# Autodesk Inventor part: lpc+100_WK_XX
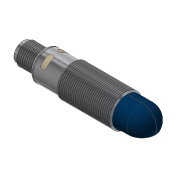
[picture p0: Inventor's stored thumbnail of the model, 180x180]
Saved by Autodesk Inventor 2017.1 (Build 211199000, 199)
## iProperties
Shininess: 20.0
Length Units: 11269
Angle Units: 11279
Time Units: 11290
Mass Units: 11283
Length Display Precision: 2
Angle Display Precision: 2
Part Number: lpc+100_WK_XX
Material: Nichtrostender Stahl - 440C
Document SubType Name: Modellieren
Description: Ipc-25 /CXX/M18
Checked By: Alves
Created: 2005-08
Designer: Ohle
Manufacturer: Standard
Standards Organization: Custom
Appearance: Aluminium - poliert
Density: 0.0
Volumn: 0.0
Area: 0.0
PropertySet Name: Model Information
Control State: 0
Master: False
Checked Out: False
BESTELLNUMMER: Ipc-25 /CXX/M18
ME: ST
Title: Ipc Sensoren
Author: Ohle
Comments: keine Bemerkung
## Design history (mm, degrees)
sketch "Skizze10"
  geometry: L1 (-43.018, 0)-(22.982, 0); L2 (-39.018, 6.5)-(-39.018, 7.25); L3 (-45.9, 8)-(-45.9, 8); L4 (-23.268, 9)-(5.732, 9); L5 (1.482, 0)-(-82.2, 0); L6 (-24.018, 8.25)-(-23.268, 9); L7 (6.482, 8.25)-(5.732, 9); L8 (-50.518, 6)-(-39.518, 6); L9 (-37.418, 8.25)-(-24.018, 8.25); L10 (-51.018, 4.5)-(-43.018, 4.5); L11 (-43.018, 0)-(-43.018, 4.5); L12 (-37.518, 8.25)-(-38.018, 8.25); L13 (-39.518, 6)-(-39.018, 6.5); L14 (-51.018, 5.5)-(-51.018, 4.5); L15 (-51.018, 5.5)-(-50.518, 6); L16 (-37.518, 8.25)-(-37.518, 8.15); L17 (-37.518, 8.15)-(-37.418, 8.15); L18 (-37.418, 8.15)-(-37.418, 8.25); L19 (6.482, 8.25)-(14.732, 8.25); L20 (22.982, 0)-(22.982, 0); A1 r 1 centre (-38.018, 7.25) between (-38.018, 8.25) and (-39.018, 7.25); A2 r 8.25 centre (14.732, 0) between (22.982, 0) and (14.732, 8.25); 4 further points
  constraints: 41 end point, 8 point on line, 5 parallel, 4 perpendicular, 4 point on circle, 4 tangent, 2 centre point, 2 horizontal, 1 collinear
  dimensions: "d171" = 4.5 distance between parallel lines of L10 L1; "d250" = 0.75 distance from line of L7.start L4; "d256" = 45 deg angle of L4 L6; "d257" = 8.25 distance between parallel lines of L5 L9; "d263" = 8.25 distance between parallel lines of L5 L12; "d266" = 12 distance from line of L2 L14.start; "d269" = 6 distance between parallel lines of L5 L8; "d289" = 135 deg angle of L7 L4; "d290" = 0.5 horizontal distance of L8.end L2.start; "d291" = 45 deg angle of L13 L8 (derived); "d293" = 0.5 horizontal distance of L14.start L8.start; "d294" = 45 deg angle of L15 L8 (derived); "d295" = 8 distance of L10.start L10.end; "d296" = 1.5 distance of L12.start point (-39.018, 8.25); "d297" = 0.1 distance of L16.end L17.end; "d298" = 8.15 distance between parallel lines of L17 L1; "d299" = 15 distance from line of L6.start L2; "d300" = 1 radius of A1; "d338" = 8.25 radius of A2; "d339" = 16.5 horizontal distance of L20.end L7.start; "d340" = 8.25 distance between parallel lines of L1 L19 (derived); "d365" = 30.5 distance of L7.start L6.start
revolve "Grundkörper pico+" sketch "Skizze10" stored, may be unused: angle "d168" = 90 deg
feature "Gewinde M12" dims "d174" = 10, "d175" = 0
feature "Gewinde M 18" dims "d179" = 10, "d180" = 0
workplane "Arbeitsebene1"
workplane "Arbeitsebene2"
sketch "Skizze13"
  geometry: L1 (-3.409, -3.409)-(3.61, 3.61); L2 (-3.439, 3.439)-(4.105, -4.105); L3 (-12.6, 0)-(12.6, 0) reference; C1 r 0.5 at (2.121, -2.121); C2 r 0.5 at (2.121, 2.121); C3 r 0.5 at (-2.121, 2.121); C4 r 0.5 at (-2.121, -2.121); C5 r 4.5 at (0, 0) reference; C6 r 0.5 at (0, 0); A1 r 3 centre (0, 0) between (-2.121, 2.121) and (2.121, 2.121); 2 further points
  constraints: 6 centre point, 6 point on line, 4 coincident, 4 end point, 4 equal radius, 4 point on circle, 1 horizontal alignment, 1 perpendicular
  dimensions: "d208" = 1 diameter of C3; "d209" = 6 diameter of A1
extrude "Pole" join sketch "Skizze13" distance "d212" = 7; taper "d213" = 0 deg
fillet "Rundung Pole" dims "d214" = 0.5
sketch "Skizze14"
  geometry: C1 r 0.5 at (0, -4.5); A1 r 4.5 centre (0, 0) between (4.435, -0.762) and (4.435, 0.762); A2 r 4.5 centre (0, 0) between (0, 4.5) and (0.499, 4.472) reference; A3 r 0.5 centre (0, 4.5) between (-0.499, 4.472) and (0.499, 4.472); 3 further points
  constraints: 9 point on circle, 3 centre point, 3 coincident, 1 horizontal alignment, 1 vertical alignment
  dimensions: "d215" = 9 diameter of A1; "d280" = 1 diameter of A3; "d330" = 1 diameter of C1
extrude "Verdrehsicherung" join sketch "Skizze14" distance "d217" = 7; taper "d218" = 0 deg
sketch "Skizze18"
  geometry: C1 r 7.25 at (0, 0) reference; C2 r 1 at (-8.15, 0)
  constraints: 1 centre point, 1 horizontal alignment
  dimensions: "d328" = 2 diameter of C2; "d329" = 8.15 distance of C1.centre C2.centre
extrude "Bohrung Ausrichtung" cut sketch "Skizze18" distance "d316" = 0.75; taper "d317" = 0 deg
workplane "Arbeitsebene4"
sketch "Skizze19"
  geometry: L1 (-39.018, 0)-(-30.18, 0); L2 (-34.718, -7.5)-(-34.718, -3); L3 (-31.718, -7.5)-(-31.718, -3); L4 (-31.718, 3)-(-31.718, 7.5); L5 (-34.718, 3)-(-34.718, 7.5); A1 r 1.5 centre (-33.218, 3) between (-31.718, 3) and (-34.718, 3); A2 r 1.5 centre (-33.218, -3) between (-34.718, -3) and (-31.718, -3); A3 r 1.5 centre (-33.218, 7.5) between (-31.718, 7.5) and (-34.718, 7.5); A4 r 1.5 centre (-33.218, -7.5) between (-34.718, -7.5) and (-31.718, -7.5); 4 further points; 1 other entity
  constraints: 10 end point, 8 point on circle, 8 tangent, 4 centre point, 3 equal radius, 2 vertical alignment, 1 horizontal, 2 other
  dimensions: "d319" = 3 diameter of A2; "d320" = 6 distance of A2.centre A1.centre; "d321" = 4.5 distance of A1.centre A3.centre; "d322" = 4.5 distance of A4.centre A2.centre; "d323" = 3 distance from line of A2.centre L1; "d324" = 5.8 dimension on A1.centre; "d325" = 5.8 dimension on A2.centre
feature "Prägen LED-Fenster" sketch "Skizze19" dims "d326" = 0.01, "d327" = 0
workplane "Arbeitsebene5"
sketch "Skizze20"
  geometry: L1 (14.732, -8.25)-(14.732, 8.25) reference; L2 (6.482, -8.25)-(6.482, 8.25) reference; L3 (14.732, -8.25)-(14.732, 8.25) reference; L4 (6.982, -8.25)-(24.008, -8.25); L5 (24.008, -8.25)-(24.008, 8.25); L6 (24.008, 8.25)-(6.982, 8.25); L7 (6.982, 8.25)-(6.982, -8.25)
  constraints: 8 end point, 2 parallel, 1 horizontal, 1 perpendicular
  dimensions: "d342" = 0.5 distance between parallel lines of L7 L2
extrude "USW-Fläche Winkelkopf" cut sketch "Skizze20" distance "d343" = 4.8; taper "d344" = 0 deg
sketch "Skizze21"
  geometry: C1 r 7 at (-14.732, 0); A1 r 7.494 centre (-14.732, 0) between (-14.732, 7.494) and (-14.732, -7.494) reference
  constraints: 1 centre point, 1 coincident
  dimensions: "d345" = 14 diameter of C1
extrude "Extrusion6" cut sketch "Skizze21" distance "d346" = 0.01; taper "d347" = 0 deg
sketch "Skizze22"
  geometry: C1 r 7 at (0, 0) reference; C2 r 5.25 at (0, 0)
  constraints: 1 centre point, 1 coincident
  dimensions: "d348" = 10.5 diameter of C2
extrude "Extrusion7" join sketch "Skizze22" distance "d349" = 0.01; taper "d350" = 0 deg
sketch "Skizze28"
  geometry: L1 (-6.482, 8.25)-(-14.732, 8.25) reference; L2 (-6.482, 8.25)-(-6.482, -8.25) reference; L3 (-14.732, -3.45)-(-22.226, -3.45) reference; L4 (-14.732, 8.15)-(-6.482, 8.15); A1 r 8.25 centre (-14.732, 0) between (-14.732, 8.25) and (-22.226, -3.45) reference; A2 r 8.15 centre (-14.732, 0) between (-14.732, 8.15) and (-22.116, -3.45)
  constraints: 2 end point, 2 point on circle, 2 point on line, 1 centre point, 1 coincident, 1 perpendicular, 1 tangent
  dimensions: "d362" = 0.1 radial gap between concentric circles of A2 A1
extrude "Extrusion8" cut sketch "Skizze28" stored distance "d363" = 0.3; taper "d364" = 0 deg
sketch "Skizze29"
  geometry: C1 r 5.5 at (0, 0); C2 r 4.5 at (0, 0); C3 r 4.15 at (0, 0); C4 r 5.25 at (0, 0); 2 further points
  constraints: 4 centre point
  dimensions: "d366" = 8.3 diameter of C3; "d367" = 10.5 diameter of C4
extrude "Extrusion9" join sketch "Skizze29" distance "d368" = 0.2; taper "d369" = 0 deg
sketch "Skizze30"
  geometry: C1 r 5.25 at (0, 0) reference; C2 r 9.601 at (0, 0); 1 further point
  constraints: 1 centre point
extrude "Extrusion10" cut sketch "Skizze30" distance "d370" = 1.8; taper "d371" = 0 deg
chamfer "Fase2" distance "d372" = 0.75; stored, may be unused: second distance "d373" = 2, angle "d374" = 30 deg
node "Volumenkörper1"
node "Volumenkörper"
node "Flächenkörper"
node "Projizierte Kontur2"
node "Projizierte Kontur3"
other parameters: "d10" = 14, "d73" = -35, "d130" = 0.2, "d207" = -95.5, "d318" = 8.25, "d341" = -8.25
